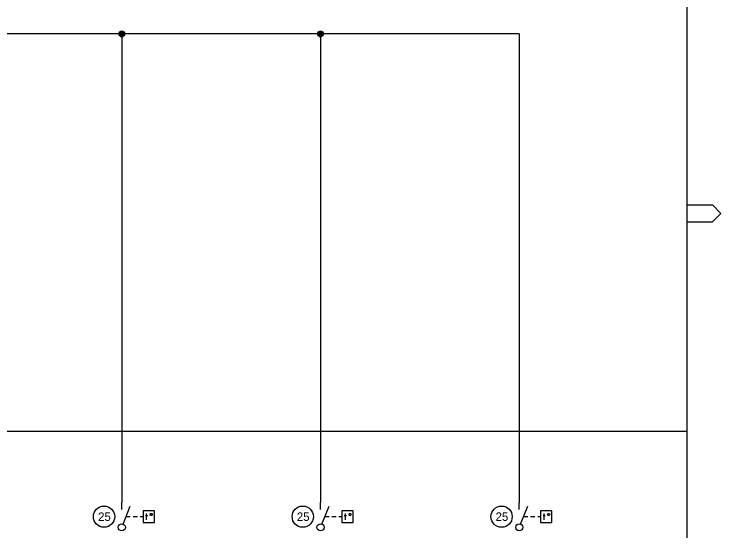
# Model space of a CAD drawing. Extents: x 0 to 841, y 0 to 594.
# Drawn here: x 592.1 to 841, y 185 to 366.9 of the extents above; entities that cross this region are included whole.
import ezdxf

# ---------------------------------------------------------------- set-up
doc = ezdxf.new("R2010")
doc.units = 0
for name, color, linetype in [('A1BORDER', 7, 'Continuous'), ('Level 1', 7, 'Continuous'), ('Level 10', 7, 'Continuous')]:
    doc.layers.add(name, color=color, linetype=linetype)

msp = doc.modelspace()

# ---------------------------------------------------------------- linework, layer by layer
at = {"layer": 'A1BORDER'}
for p, q in [((829, 581), (829, 15)), ((829, 299.76), (838, 299.76)), ((838, 299.76), (841, 296.76)), ((838, 293.76), (841, 296.76)), ((829, 293.76), (838, 293.76))]:
    msp.add_line(p, q, dxfattribs=at)
at = {"layer": 'Level 1'}
for p, q in [((770, 360), (420, 360)), ((630, 360), (630, 195)), ((700, 360), (700, 195)), ((770, 360), (770, 195)), ((829, 220), (28, 220)), ((630, 192.5), (630, 195)), ((700, 192.5), (700, 195)), ((770, 192.5), (770, 195)), ((630.46, 187.41), (633, 193.75)), ((700.46, 187.41), (703, 193.75)), ((770.46, 187.41), (773, 193.75)), ((631.5, 190), (633, 190)), ((634, 190), (635.5, 190)), ((636.5, 190), (637.5, 190)), ((701.5, 190), (703, 190)), ((704, 190), (705.5, 190)), ((706.5, 190), (707.5, 190)), ((771.5, 190), (773, 190)), ((774, 190), (775.5, 190)), ((776.5, 190), (777.5, 190))]:
    msp.add_line(p, q, dxfattribs=at)
for points in [[(637.5, 188), (641.5, 188), (641.5, 192), (637.5, 192)], [(707.5, 188), (711.5, 188), (711.5, 192), (707.5, 192)], [(777.5, 188), (781.5, 188), (781.5, 192), (777.5, 192)]]:
    msp.add_lwpolyline(points, close=True, dxfattribs=at)
for points in [[(638.38, 190.38), (639.13, 190.38)], [(638.63, 191.13), (638.63, 188.87)], [(640.36, 190.38), (640.18, 190.42), (640.05, 190.56), (639.99, 190.76), (640.05, 190.94), (640.18, 191.07), (640.36, 191.13), (640.56, 191.07), (640.7, 190.94), (640.74, 190.76), (640.7, 190.56), (640.56, 190.42), (640.36, 190.38)], [(708.38, 190.38), (709.13, 190.38)], [(708.63, 191.13), (708.63, 188.87)], [(710.36, 190.38), (710.18, 190.42), (710.05, 190.56), (709.99, 190.76), (710.05, 190.94), (710.18, 191.07), (710.36, 191.13), (710.56, 191.07), (710.7, 190.94), (710.74, 190.76), (710.7, 190.56), (710.56, 190.42), (710.36, 190.38)], [(778.38, 190.38), (779.13, 190.38)], [(778.63, 191.13), (778.63, 188.87)], [(780.36, 190.38), (780.18, 190.42), (780.05, 190.56), (779.99, 190.76), (780.05, 190.94), (780.18, 191.07), (780.36, 191.13), (780.56, 191.07), (780.7, 190.94), (780.74, 190.76), (780.7, 190.56), (780.56, 190.42), (780.36, 190.38)]]:
    msp.add_lwpolyline(points, dxfattribs=at)
for centre, radius in [((623.75, 190), 3.75), ((693.75, 190), 3.75), ((763.75, 190), 3.75), ((630, 186.25), 1.25), ((700, 186.25), 1.25), ((770, 186.25), 1.25)]:
    msp.add_circle(centre, radius, dxfattribs=at)
at = {"layer": 'Level 10'}
for p, q in [((630, 361), (630, 361)), ((700, 361), (700, 361)), ((629, 360), (630.99, 360)), ((629.05, 360.3), (630.95, 360.3)), ((629.05, 359.7), (630.95, 359.7)), ((629.2, 360.6), (630.8, 360.6)), ((629.2, 359.4), (630.8, 359.4)), ((629.56, 360.9), (630.44, 360.9)), ((629.56, 359.1), (630.44, 359.1)), ((699, 360), (700.99, 360)), ((699.05, 360.3), (700.95, 360.3)), ((699.05, 359.7), (700.95, 359.7)), ((699.2, 360.6), (700.8, 360.6)), ((699.2, 359.4), (700.8, 359.4)), ((699.56, 360.9), (700.44, 360.9)), ((699.56, 359.1), (700.44, 359.1))]:
    msp.add_line(p, q, dxfattribs=at)
for centre in [(630, 360), (700, 360)]:
    msp.add_circle(centre, 1, dxfattribs=at)

# ---------------------------------------------------------------- texts
at = {"layer": 'Level 1'}
for p in [(621.66, 188.5), (691.66, 188.5), (761.66, 188.5)]:
    msp.add_text('25', height=3, dxfattribs=at).set_placement(p)

doc.saveas('drawing.dxf')
